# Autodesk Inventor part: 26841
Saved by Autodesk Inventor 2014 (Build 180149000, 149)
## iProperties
Shininess: 27.0
Length Units: 11272
Angle Units: 11279
Time Units: 11290
Mass Units: 11286
Length Display Precision: 3
Angle Display Precision: 2
Compacted: True
Category: Hydraulics
Company: Autodesk, Inc.
Created: 2001-05
Part Number: 26841
Material: Steel, Mild
Catalog Web Link: http://www.aeroquip.com
Description: FITTING; ST-BQ4-S
Document SubType Name: Modeling
Designer: Autodesk, Inc.
Density: 7.75 g/cm^3
Appearance: Yellow Zinc
Density: 7.86
Volumn: 7.3241227782804
Area: 41.16363820292827
PropertySet Name: Model Information
Control State: 0
Master: False
Checked Out: False
Last Check In By: JT
Last Check In Date: 2003-06-20
Title: FITTING; ST-BQ4-S
Author: Autodesk, Inc.
Comments: -
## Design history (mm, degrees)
sketch "Sketch2"
  geometry: L1 (-9.501, 2.105)-(-4.001, 11.63); L2 (-4.001, 11.63)-(6.997, 11.63); L3 (6.997, 11.63)-(12.496, 2.105); L4 (12.496, 2.105)-(6.997, -7.42); L5 (6.997, -7.42)-(-4.001, -7.42); L6 (-4.001, -7.42)-(-9.501, 2.105); C1 r 9.525 at (1.498, 2.105); 1 further point
  constraints: 12 end point, 5 tangent, 3 equal length, 3 parallel, 1 centre point, 1 coincident, 1 horizontal
  dimensions: "d0" = 19.05 diameter of C1 (derived)
feature "Hexagon_flats_join1" sketch "Sketch2"
sketch "Sketch1"
  geometry: L1 (26.67, 5.499)-(26.67, -5.499) reference; L2 (26.67, 0)-(35.306, 0); L3 (26.67, 6.858)-(26.67, 0); L4 (35.306, 0)-(35.306, 6.636); L5 (35.306, 6.636)-(26.67, 6.858); L6 (0, 0)-(48.938, 0)
  constraints: 10 end point, 2 horizontal, 1 collinear, 1 midpoint, 1 parallel
  dimensions: "npt_major_od_1" = 13.716 diameter of L3.start L2; "npt_minor_od" = 13.27277 diameter of L4.end L2 (derived); "d96" = 35.306 distance from line of L4 L6.start (= npt_length_1); "d97" = 1.47 deg angle of L2 L5
revolve "Revolution1" sketch "Sketch1" stored, may be unused: angle "d16" = 90 deg
sketch "Sketch5"
  geometry: L1 (0, 5.499)-(0, 10.999) reference; L2 (26.67, 10.999)-(26.67, 5.499) reference; L3 (-5.334, 0)-(32.004, 0) reference; L4 (26.67, 10.999)-(0, 10.999); L5 (0.395, 10.999)-(0, 9.525); L6 (26.275, 10.999)-(26.67, 9.525)
  constraints: 6 end point, 4 point on line, 1 horizontal alignment, 1 parallel
  dimensions: "d38" = 15 deg angle of L1 L5; "d39" = 15 deg angle of L2 L6 (= d38); "d43" = 19.05 diameter of L5.end L3 (= hex_size)
revolve "Revolution2" sketch "Sketch5" stored, may be unused: angle "d42" = 90 deg
thread "Thread2" dims "d74" = 25.4, "d75" = 0
sketch "Sketch9"
  geometry: C1 r 6.636 at (0, 0) reference; 1 further point
  constraints: 1 coincident
hole "Hole5" sketch "Sketch9" at (0, 0) diameter "npt_hole_dia_1" = 7.1374; stored, may be unused: countersink angle "d80" = 82 deg, drill point angle "d82" = 118 deg; dims "d77" = 12.7, "d78" = 9.525, "d79" = 6.35, "npt_hole_dpth" = 21.971 (derived)
sketch "Sketch11"
  geometry: C1 r 6.858 at (0, 0); A1 r 9.525 centre (0, 0) between (-4.763, 8.249) and (-9.525, 0) reference
  constraints: 1 centre point, 1 coincident
  dimensions: "FNPT_hole_dia" = 13.716 diameter of C1
extrude "Extrusion1" cut sketch "Sketch11" taper "d100" = -1.47 deg; distance "FNPT_hole_depth" = 20.0025
thread "Thread6" dims "d101" = 25.4, "d102" = 0
body "Solid1"
other parameters: "hex_size" = 19.05 [user parameter; used in 2 equation terms], "hex_thickness" = 26.67 [user parameter; used in 1 equation term], "npt_length_1" = 35.306
